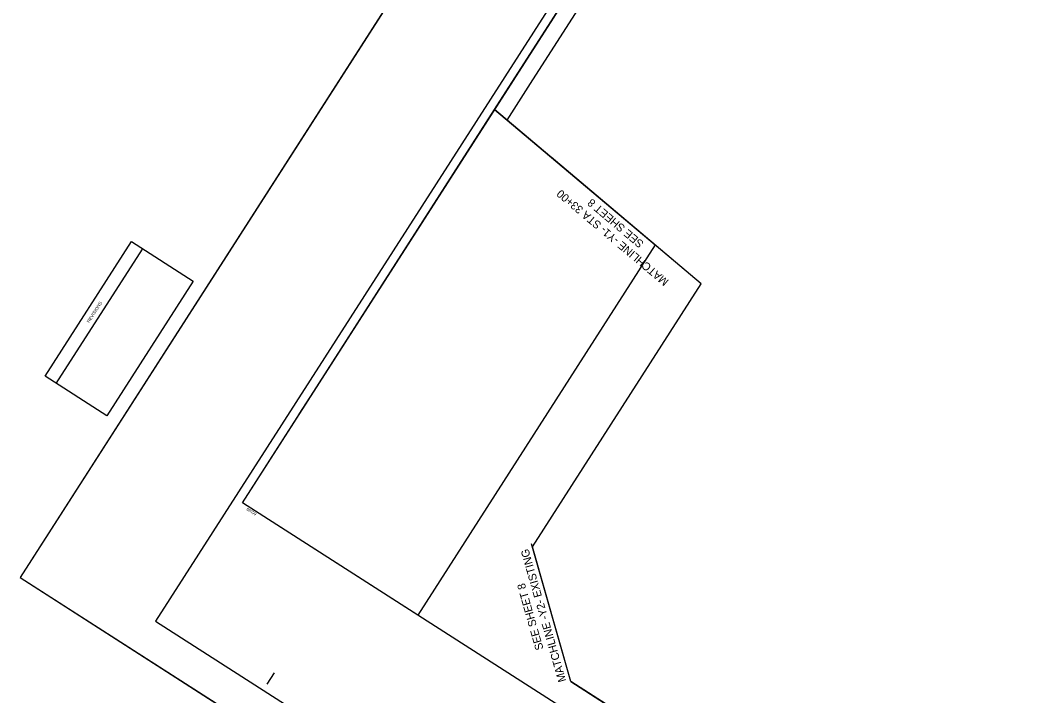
# Model space of a CAD drawing. Extents: x 2346049 to 2349719, y 842061 to 846435.
# Drawn here: x 2346049 to 2347924, y 843164 to 844432 of the extents above; entities that cross this region are included whole.
import ezdxf

# ---------------------------------------------------------------- set-up
doc = ezdxf.new("R2010")
doc.units = 0
for name, color, linetype in [('Default', 7, 'Continuous'), ('Matchline', 7, 'Continuous'), ('Matchline Text', 7, 'Continuous'), ('Scratch_Level_0', 7, 'Continuous'), ('Sheet Cutting Line CELL', 7, 'Continuous'), ('Sheet Detail CELL', 7, 'Continuous'), ('Sheet Plot Border Inside CELL', 7, 'Continuous'), ('Sheet Plot Border Outside CELL', 7, 'Continuous')]:
    doc.layers.add(name, color=color, linetype=linetype)

msp = doc.modelspace()

# ---------------------------------------------------------------- linework, layer by layer
at = {"layer": 'Default'}
for p, q in [((2347324.8, 843936.9), (2346961.1, 844244)), ((2347048.1, 844170.5), (2347048.1, 844170.5))]:
    msp.add_line(p, q, dxfattribs=at)
at = {"layer": 'Matchline'}
msp.add_line((2347080.7, 843191.4), (2347549.3, 842890.9), dxfattribs=at)
for points in [[(2347324.8, 843936.9), (2347043.8, 844174.2), (2347043.8, 844174.2), (2347043.8, 844174.2)], [(2347080.7, 843191.4), (2347006.9, 843449.8), (2347006.9, 843449.8), (2347006.9, 843449.8)]]:
    msp.add_lwpolyline(points, dxfattribs=at)
at = {"layer": 'Scratch_Level_0'}
for points in [[(2349350.4, 845074.8), (2348851.8, 844297.2), (2348757.8, 844341), (2348462.4, 843706.5), (2348375.3, 843541.3), (2348255.5, 843353.8), (2348231.9, 843354.7), (2348207.8, 843279), (2348000.9, 842955.2), (2347829, 843060.7), (2347638.3, 842833.8), (2347080.7, 843191.4), (2347008.6, 843443.9), (2347324.8, 843936.9), (2346937.8, 844263.6), (2347160.2, 844610.4)], [(2349350.4, 845074.8), (2348851.8, 844297.2), (2348757.8, 844341), (2348462.4, 843706.5), (2348375.3, 843541.3), (2348255.5, 843353.8), (2348231.9, 843354.7), (2348207.8, 843279), (2348000.9, 842955.2), (2347829, 843060.7), (2347638.3, 842833.8), (2347080.7, 843191.4), (2347008.6, 843443.9), (2347324.8, 843936.9), (2346961.1, 844244), (2347005, 844312.5), (2347188.2, 844598.2)], [(2349350.4, 845074.8), (2348851.8, 844297.2), (2348757.8, 844341), (2348462.4, 843706.5), (2348375.3, 843541.3), (2348255.5, 843353.8), (2348231.9, 843354.7), (2348207.8, 843279), (2348000.9, 842955.2), (2347829, 843060.7), (2347638.3, 842833.8), (2347080.7, 843191.4), (2347008.6, 843443.9), (2347324.8, 843936.9), (2346961.1, 844244), (2347005, 844312.5), (2347188.2, 844598.2)]]:
    msp.add_lwpolyline(points, dxfattribs=at)
msp.add_lwpolyline([(2346465.3, 843526.7), (2346937.8, 844263.6), (2347238.7, 844010.1), (2346793.7, 843316.1)], close=True, dxfattribs=at)
at = {"layer": 'Sheet Cutting Line CELL'}
for p, q in [((2347866.8, 846221.5), (2346048.7, 843386.4)), ((2346048.7, 843386.4), (2347900.5, 842198.8))]:
    msp.add_line(p, q, dxfattribs=at)
at = {"layer": 'Sheet Detail CELL'}
for p, q in [((2346116.6, 843750.3), (2346278.2, 844002.3)), ((2346196.4, 843875.3), (2346196.4, 843875.3)), ((2346571.9, 843693), (2346625.4, 843776)), ((2346571.9, 843693), (2346571.9, 843693)), ((2346465.3, 843526.7), (2346465.3, 843526.7)), ((2346511.9, 843186.8), (2346525.4, 843207.8))]:
    msp.add_line(p, q, dxfattribs=at)
for points in [[(2346465.3, 843526.7), (2348084.7, 846052), (2349473.7, 845161.3), (2347854.2, 842636)], [(2346095.6, 843763.8), (2346257.5, 844016.3), (2346373.3, 843942.1), (2346211.3, 843689.6)]]:
    msp.add_lwpolyline(points, close=True, dxfattribs=at)
at = {"layer": 'Sheet Plot Border Inside CELL'}
msp.add_lwpolyline([(2348083.9, 846082.3), (2346302.5, 843304.4), (2347720, 842395.3), (2349501.5, 845173.2)], close=True, dxfattribs=at)
at = {"layer": 'Sheet Plot Border Outside CELL'}
msp.add_lwpolyline([(2347866.8, 846221.5), (2346048.7, 843386.4), (2347900.5, 842198.8), (2349718.7, 845033.9)], close=True, dxfattribs=at)

# ---------------------------------------------------------------- texts
at = {"layer": 'Matchline Text'}
for s, rotation, p in [('MATCHLINE -Y1- STA 33+00', 139.8208, (2347265.2, 843943.2)), ('SEE SHEET 8', 139.8208, (2347218.6, 844014.4)), ('MATCHLINE -Y2- EXISTING', 105.9371, (2347072, 843192.9)), ('SEE SHEET 8', 105.9371, (2347029.6, 843252.7))]:
    msp.add_text(s, height=15, rotation=rotation, dxfattribs=at).set_placement(p)
at = {"layer": 'Sheet Detail CELL'}
for s, height, rotation, p in [('REVISIONS', 6, 57.3281, (2346178.4, 843863.3)), ('6/2/99', 5.25, 147.3281, (2346492.3, 843506.8))]:
    msp.add_text(s, height=height, rotation=rotation, dxfattribs=at).set_placement(p)

doc.saveas('drawing.dxf')
